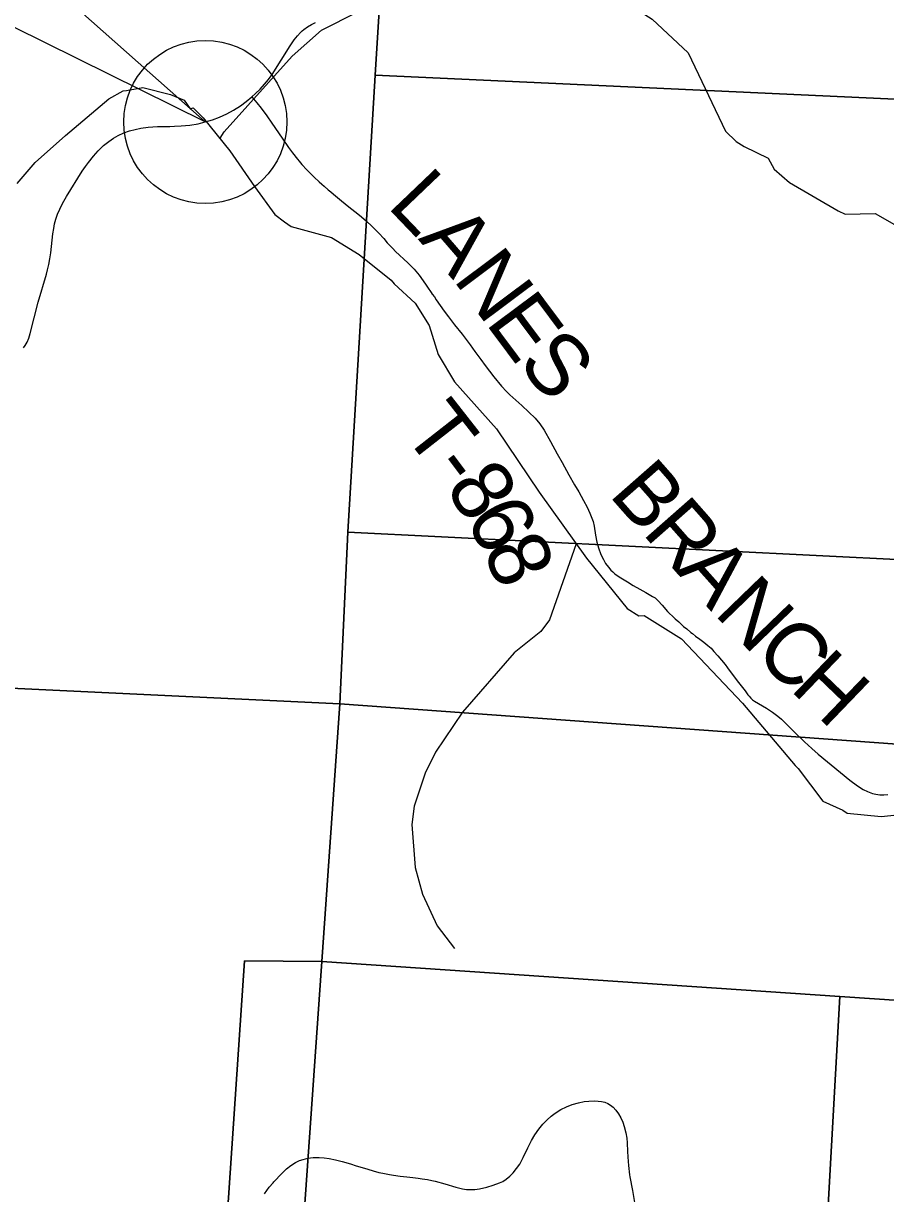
# Model space of a CAD drawing. Extents: x -2.1 to 31.9, y 6.3 to 28.3.
# Drawn here: x 3.117 to 3.912, y 22.446 to 23.525 of the extents above; entities that cross this region are included whole.
import ezdxf

# ---------------------------------------------------------------- set-up
doc = ezdxf.new("R2010")
doc.units = 0
for name, color, linetype in [('GM_X_County_Road', 7, 'Continuous'), ('GM_X_Minor_River', 7, 'Continuous'), ('GM_X_Minor_River_Text', 7, 'Continuous'), ('GM_X_Section', 7, 'Continuous'), ('GM_X_State_Route', 7, 'Continuous'), ('GM_X_Township_Road', 7, 'Continuous'), ('GM_X_Township_Road_Text', 7, 'Continuous'), ('TX_P_1', 7, 'Continuous')]:
    doc.layers.add(name, color=color, linetype=linetype)

msp = doc.modelspace()

# ---------------------------------------------------------------- linework, layer by layer
at = {"layer": 'GM_X_County_Road'}
msp.add_lwpolyline([(3.339, 22.4461), (3.3413, 22.449), (3.3435, 22.452), (3.347, 22.4563), (3.3478, 22.4572), (3.355, 22.4649), (3.3594, 22.4692), (3.3633, 22.4722), (3.3675, 22.4748), (3.3713, 22.4766), (3.3748, 22.4778), (3.379, 22.4788), (3.3838, 22.4794), (3.3894, 22.4795), (3.3941, 22.4793), (3.3986, 22.4787), (3.4046, 22.4774), (3.4082, 22.4765), (3.4106, 22.4759), (3.4183, 22.4737), (3.4236, 22.4719), (3.429, 22.4703), (3.4343, 22.4686), (3.4391, 22.4673), (3.4445, 22.4658), (3.4481, 22.465), (3.4542, 22.4638), (3.4579, 22.4632), (3.464, 22.4624), (3.4702, 22.4617), (3.4757, 22.4611), (3.4806, 22.4605), (3.4843, 22.4599), (3.4892, 22.4592), (3.4934, 22.4584), (3.4964, 22.4577), (3.5053, 22.4551), (3.5155, 22.4521), (3.5216, 22.4507), (3.5253, 22.4501), (3.5291, 22.4499), (3.5328, 22.45), (3.5372, 22.4506), (3.5439, 22.4522), (3.5499, 22.4539), (3.5558, 22.4561), (3.5586, 22.4574), (3.5618, 22.4595), (3.5651, 22.4624), (3.5682, 22.4655), (3.5714, 22.4693), (3.5743, 22.4735), (3.5776, 22.4795), (3.5819, 22.4884), (3.5853, 22.4951), (3.5883, 22.5004), (3.5918, 22.5055), (3.5957, 22.5103), (3.5995, 22.5143), (3.6032, 22.5176), (3.6071, 22.5205), (3.6123, 22.5238), (3.6173, 22.5263), (3.6225, 22.5283), (3.6284, 22.53), (3.6338, 22.531), (3.6381, 22.5315), (3.643, 22.5317), (3.6467, 22.5316), (3.6497, 22.5312), (3.6526, 22.5305), (3.6554, 22.5293), (3.658, 22.5278), (3.6603, 22.5259), (3.6628, 22.5232), (3.6653, 22.5197), (3.6675, 22.516), (3.6692, 22.5121), (3.6706, 22.5081), (3.6721, 22.5021), (3.6729, 22.4973), (3.6733, 22.4931), (3.6736, 22.4851), (3.6738, 22.4802), (3.6742, 22.4759), (3.6745, 22.4722), (3.6756, 22.4636), (3.6759, 22.4618), (3.6781, 22.449), (3.6813, 22.4306)], dxfattribs=at)
at = {"layer": 'GM_X_Minor_River'}
for points in [[(3.2983, 23.4195), (3.3019, 23.4253), (3.3645, 23.4951), (3.3917, 23.5189), (3.4251, 23.5361), (3.4566, 23.5643), (3.4737, 23.5808), (3.4906, 23.5902), (3.5346, 23.6066), (3.5785, 23.6082), (3.6033, 23.6044), (3.6178, 23.5952), (3.6515, 23.5581), (3.6963, 23.5293), (3.7294, 23.4982), (3.7639, 23.4258), (3.7738, 23.4163), (3.7812, 23.4119), (3.8032, 23.401), (3.8089, 23.3909), (3.8229, 23.3787), (3.8679, 23.3525)], [(3.1111, 23.3777), (3.1277, 23.3971), (3.1556, 23.4219), (3.1957, 23.4558), (3.2089, 23.4631), (3.2119, 23.4635), (3.227, 23.4662), (3.2524, 23.4598), (3.2649, 23.4545), (3.2705, 23.4465), (3.2732, 23.4473), (3.2826, 23.4382), (3.3072, 23.4078), (3.33, 23.3748), (3.3485, 23.349), (3.3576, 23.3422), (3.3636, 23.338), (3.4007, 23.3279), (3.4264, 23.3123), (3.4559, 23.2885), (3.4586, 23.285), (3.4779, 23.2672), (3.4907, 23.2467), (3.4991, 23.2201), (3.5142, 23.1947), (3.5528, 23.1515), (3.5922, 23.093), (3.6357, 23.0323), (3.6732, 22.9857), (3.6841, 22.9789), (3.6891, 22.9793), (3.7235, 22.9577), (3.7795, 22.8985), (3.8283, 22.8409), (3.8309, 22.8382), (3.8537, 22.8082), (3.8722, 22.7999), (3.876, 22.7969), (3.9073, 22.7939), (3.9338, 22.7966)], [(3.8679, 23.3525), (3.8742, 23.3493), (3.9018, 23.35), (3.9219, 23.3387), (3.9343, 23.325), (3.9767, 23.3024), (4.0135, 23.2708), (4.0208, 23.2604), (4.0352, 23.225), (4.0381, 23.2188), (4.0872, 23.1929), (4.1369, 23.1891), (4.1637, 23.1852), (4.2236, 23.1684), (4.2448, 23.1674), (4.2659, 23.1648), (4.3296, 23.1366), (4.3553, 23.1342), (4.3916, 23.1471), (4.4355, 23.151), (4.4567, 23.1648), (4.4629, 23.1688), (4.5008, 23.196)], [(3.6262, 23.0455), (3.6016, 22.9753), (3.5938, 22.9646), (3.5693, 22.9448), (3.5216, 22.8902), (3.4966, 22.8534), (3.487, 22.8339), (3.477, 22.8035), (3.475, 22.7865), (3.4779, 22.7469), (3.4847, 22.7224), (3.4982, 22.6931), (3.5142, 22.6721)]]:
    msp.add_lwpolyline(points, dxfattribs=at)
at = {"layer": 'GM_X_Section'}
for points in [[(2.4194, 23.947), (3.4671, 23.8965), (3.4412, 23.4777), (3.416, 23.0562), (3.4084, 22.8979), (2.8085, 22.9264), (2.3612, 22.9526), (2.3614, 22.9562), (2.3709, 23.1348), (2.3938, 23.5483)], [(3.4671, 23.8965), (4.5062, 23.8498), (4.4791, 23.4295), (3.4412, 23.4777)], [(4.4791, 23.4295), (4.4518, 23.0046), (3.416, 23.0562), (3.4412, 23.4777)], [(3.416, 23.0562), (4.4518, 23.0046), (4.4401, 22.8231), (3.4084, 22.8979)], [(3.4084, 22.8979), (3.3918, 22.6602), (3.3206, 22.6609), (3.2816, 22.083), (2.758, 22.1083), (2.8085, 22.9264)], [(4.4401, 22.8231), (4.4397, 22.818), (4.4255, 22.5906), (3.8692, 22.6281), (3.3918, 22.6602), (3.4084, 22.8979)], [(3.3918, 22.6602), (3.333, 21.819), (3.264, 21.8222), (3.2816, 22.083), (3.3206, 22.6609)], [(3.8692, 22.6281), (3.823, 21.7961), (3.333, 21.819), (3.3918, 22.6602)], [(4.4255, 22.5906), (4.3744, 21.7716), (3.823, 21.7961), (3.8692, 22.6281)]]:
    msp.add_lwpolyline(points, close=True, dxfattribs=at)
at = {"layer": 'GM_X_State_Route'}
msp.add_lwpolyline([(3.1168, 23.2262), (3.1184, 23.2282), (3.1202, 23.2313), (3.1218, 23.2349), (3.1232, 23.2393), (3.1306, 23.2683), (3.138, 23.2939), (3.1391, 23.298), (3.1402, 23.3029), (3.1412, 23.3083), (3.142, 23.3138), (3.1441, 23.3313), (3.1449, 23.3363), (3.1456, 23.3404), (3.1468, 23.3447), (3.1484, 23.3493), (3.1504, 23.354), (3.1529, 23.3592), (3.1566, 23.3658), (3.171, 23.3889), (3.174, 23.3932), (3.1768, 23.397), (3.1814, 23.4028), (3.1859, 23.4079), (3.1908, 23.4126), (3.1955, 23.4165), (3.2, 23.4196), (3.2043, 23.422), (3.2093, 23.4243), (3.2145, 23.4261), (3.2198, 23.4276), (3.2252, 23.4287), (3.232, 23.4295), (3.2406, 23.4301), (3.2517, 23.4303), (3.2561, 23.4304), (3.2623, 23.4308), (3.2704, 23.4316), (3.2778, 23.4328), (3.2845, 23.4344), (3.2911, 23.4364), (3.2976, 23.4388), (3.3044, 23.4419), (3.3105, 23.4452), (3.3168, 23.4493), (3.3223, 23.4534), (3.3274, 23.4576), (3.3309, 23.4608), (3.335, 23.4647), (3.3392, 23.4692), (3.3428, 23.4736), (3.3461, 23.4782), (3.3626, 23.5045), (3.3663, 23.5101), (3.3694, 23.5139), (3.3721, 23.517), (3.3737, 23.5184), (3.3754, 23.5197), (3.3787, 23.522), (3.3825, 23.5242), (3.3861, 23.5261)], dxfattribs=at)
at = {"layer": 'GM_X_Township_Road'}
for points in [[(3.3274, 23.4576), (3.3321, 23.4519), (3.3361, 23.447), (3.3413, 23.44), (3.3458, 23.4333), (3.3552, 23.4194), (3.3613, 23.4108), (3.365, 23.4059), (3.3695, 23.4), (3.371, 23.3981), (3.3734, 23.3953), (3.3781, 23.3903), (3.3859, 23.3825), (3.3886, 23.38), (3.3895, 23.3791), (3.3918, 23.3771), (3.3941, 23.3751), (3.3978, 23.3718), (3.4002, 23.3699), (3.4026, 23.3679), (3.4082, 23.3632), (3.4154, 23.3573), (3.4265, 23.3484), (3.4327, 23.3431), (3.4382, 23.3381), (3.4444, 23.3319), (3.4489, 23.3268), (3.4522, 23.323), (3.4551, 23.3198), (3.4574, 23.3177), (3.4599, 23.3151), (3.4713, 23.3045), (3.477, 23.2987), (3.4815, 23.2932), (3.4876, 23.2848), (3.4893, 23.2822), (3.4927, 23.277), (3.4937, 23.2755), (3.4956, 23.273), (3.4973, 23.2705), (3.5048, 23.2598), (3.5087, 23.2548), (3.5143, 23.2474), (3.5212, 23.2388), (3.5286, 23.2288), (3.533, 23.2228), (3.5386, 23.2153), (3.5426, 23.2098), (3.5505, 23.1994), (3.5575, 23.1909), (3.5621, 23.1859), (3.5651, 23.1827), (3.5706, 23.1778), (3.5761, 23.1728), (3.5826, 23.1669), (3.5884, 23.1612), (3.5928, 23.1559), (3.5967, 23.1502), (3.6026, 23.1399), (3.6088, 23.1284), (3.6133, 23.1203), (3.6196, 23.1089), (3.6249, 23.0998), (3.6287, 23.0934), (3.6331, 23.0854), (3.6365, 23.0791), (3.639, 23.0736), (3.6419, 23.066), (3.643, 23.0617), (3.6441, 23.0534), (3.6454, 23.0469), (3.6469, 23.0417), (3.6491, 23.0357), (3.6514, 23.031), (3.6535, 23.0273), (3.656, 23.0238), (3.6584, 23.0211), (3.66, 23.0196), (3.662, 23.0178), (3.6659, 23.015), (3.6737, 23.0102), (3.679, 23.0071), (3.685, 23.0037), (3.6904, 23.0006), (3.6968, 22.9968), (3.699, 22.9955), (3.7018, 22.9929), (3.7056, 22.9887), (3.7104, 22.9831), (3.7121, 22.9813), (3.7153, 22.9783), (3.7175, 22.9762), (3.7208, 22.9734), (3.7231, 22.9714), (3.7254, 22.9693), (3.7283, 22.967), (3.732, 22.9637), (3.7335, 22.9626), (3.7364, 22.9603), (3.7404, 22.9574), (3.7439, 22.9548), (3.7478, 22.9516), (3.7506, 22.9491), (3.7533, 22.9462), (3.7569, 22.942), (3.7636, 22.934), (3.7658, 22.931), (3.7748, 22.9192), (3.7808, 22.9114)], [(3.7808, 22.9114), (3.782, 22.9099), (3.7834, 22.9079), (3.7845, 22.9062), (3.7857, 22.9048), (3.7873, 22.9032), (3.7889, 22.9016), (3.7908, 22.9002), (3.8016, 22.8939), (3.8073, 22.8902), (3.8123, 22.8866), (3.8156, 22.8838), (3.8209, 22.8786), (3.827, 22.8724), (3.8367, 22.8628), (3.8435, 22.8566), (3.8495, 22.8515), (3.87, 22.8345), (3.8786, 22.8274), (3.8857, 22.8223), (3.8909, 22.819), (3.8948, 22.817), (3.8995, 22.8153), (3.9025, 22.8145), (3.9061, 22.814), (3.9098, 22.8139), (3.9136, 22.8141)]]:
    msp.add_lwpolyline(points, dxfattribs=at)
at = {"layer": 'TX_P_1'}
msp.add_lwpolyline([(2.6072, 24.0345), (3.2845, 23.4344), (2.6072, 23.7698)], close=True, dxfattribs=at)
msp.add_circle((3.2845, 23.4344), 0.0752, dxfattribs=at)

# ---------------------------------------------------------------- texts
at = {"layer": 'GM_X_Minor_River_Text'}
msp.add_text('Creek', height=0.09469, rotation=236.1304, dxfattribs=at).set_placement((3.0983, 23.6674))
at = {"layer": 'GM_X_Township_Road_Text'}
for s, rotation, p in [('L', 313.7196, (3.4512, 23.3566)), ('A', 310.7937, (3.4801, 23.3265)), ('N', 306.8054, (3.5121, 23.2894)), ('E', 306.7165, (3.542, 23.2494)), ('S', 312.0447, (3.5711, 23.2109)), ('T', 308.0554, (3.4653, 23.1483)), ('-', 306.8199, (3.4913, 23.1151)), ('8', 303.4072, (3.5048, 23.0971)), ('B', 311.3477, (3.6555, 23.0907)), ('6', 298.8464, (3.5234, 23.0689)), ('R', 311.3464, (3.6863, 23.0556)), ('8', 293.6243, (3.5397, 23.0395)), ('A', 311.6869, (3.7174, 23.0203)), ('N', 314.0513, (3.7524, 22.9811)), ('C', 315.9732, (3.7886, 22.9437)), ('H', 316.1221, (3.8223, 22.9112))]:
    msp.add_text(s, height=0.0568, rotation=rotation, dxfattribs=at).set_placement(p)

doc.saveas('drawing.dxf')
